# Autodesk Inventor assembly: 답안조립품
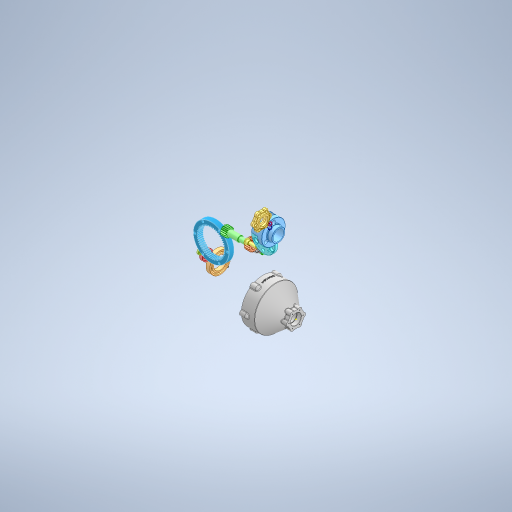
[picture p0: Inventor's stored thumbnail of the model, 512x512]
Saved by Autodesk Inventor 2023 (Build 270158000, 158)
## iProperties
Created: 2026-05
Part Number: 답안조립품
Document SubType Name: Assembly
Designer: home
Author: home
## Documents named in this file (19)
- C:\Users\home\Desktop\760503V1005\답안조립품.iam
- C:\Users\home\Desktop\760503V1005\본체.ipt
- C:\Users\home\Desktop\760403V1014\6각 구멍붙이 볼트 M4x10.ipt
- C:\Users\home\Desktop\760403V1014\6각 구멍붙이 볼트 M4x20.ipt
- C:\Users\home\Desktop\760403V1014\6각 구멍붙이 볼트 M6x10.ipt
- C:\Users\home\Desktop\760403V1014\깊은 홈 볼 베어링 6010.ipt
- C:\Users\home\Desktop\760403V1014\깊은 홈 볼 베어링 6203.ipt
- C:\Users\home\Desktop\760403V1014\깊은 홈 볼 베어링 6900.ipt
- C:\Users\home\Desktop\760403V1014\링 기어.ipt
- C:\Users\home\Desktop\760403V1014\선 기어 축.ipt
- C:\Users\home\Desktop\760403V1014\엔드 캡.ipt
- C:\Users\home\Desktop\760403V1014\오일 실 17 32 8.ipt
- C:\Users\home\Desktop\760403V1014\유성 기어.ipt
- C:\Users\home\Desktop\760403V1014\유성 축.ipt
- C:\Users\home\Desktop\760403V1014\유성 캐리어 커버.ipt
- C:\Users\home\Desktop\760403V1014\유성 캐리어.ipt
- C:\Users\home\Desktop\760403V1014\축용 C형 멈춤링 17.ipt
- C:\Users\home\Desktop\760403V1014\칼라.ipt
- C:\Users\home\Desktop\760403V1014\커버.ipt
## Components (3 placed, 3 different names)
1. 6각 구멍붙이 볼트 M4x10:1
2. 6각 구멍붙이 볼트 M4x20:1
3. 6각 구멍붙이 볼트 M6x10:1
